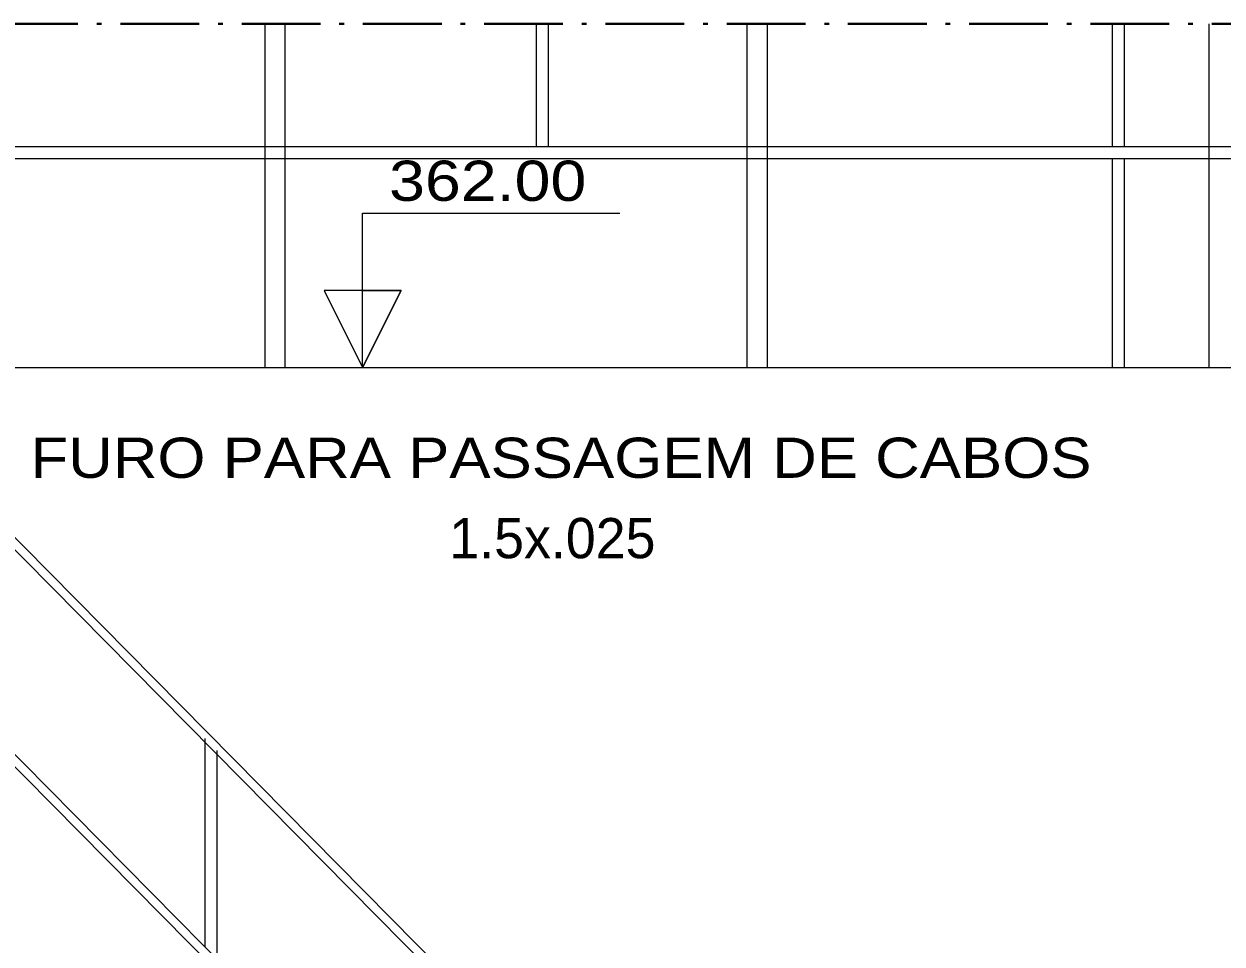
# Model space of a CAD drawing. Extents: x -4160 to -2690, y -474 to 714.
# Drawn here: x -3633.03 to -3590.42, y -282.79 to -250.08 of the extents above; entities that cross this region are included whole.
import ezdxf
from ezdxf.enums import TextEntityAlignment as Align

# ---------------------------------------------------------------- set-up
doc = ezdxf.new("R2010")
doc.units = 0
doc.header["$LTSCALE"] = 0.56
doc.linetypes.add('DOT_DASHED', pattern=[7.7, 5, -1.2, 0.3, -1.2])
for name, color, linetype, lineweight in [('10', 7, 'Continuous', 35), ('13', 7, 'Continuous', 13), ('2', 7, 'Continuous', 25), ('63', 7, 'Continuous', 13), ('9', 7, 'Continuous', 13)]:
    doc.layers.add(name, color=color, linetype=linetype, lineweight=lineweight)

msp = doc.modelspace()

# ---------------------------------------------------------------- linework, layer by layer
at = {"layer": '10', "lineweight": 13}
msp.add_line((-3651.4113, -250.077), (-3593.7271, -308.4155), dxfattribs=at)
at = {"layer": '13'}
for p, q in [((-3651.8384, -250.077), (-3594.1556, -308.4141)), ((-3614.8185, -250.077), (-3614.8185, -254.4298)), ((-3614.3899, -250.077), (-3614.3899, -254.4298)), ((-3594.3299, -250.077), (-3594.3299, -254.4298)), ((-3593.9013, -250.077), (-3593.9013, -254.4298)), ((-3654.8756, -254.287), (-3594.1556, -315.6941)), ((-3654.8756, -254.7198), (-3594.1556, -316.1283)), ((-3647.107, -254.4298), (-3573.9042, -254.4298)), ((-3646.6827, -254.8584), (-3573.9042, -254.8584)), ((-3594.3299, -254.8584), (-3594.3299, -262.287)), ((-3593.9013, -254.8584), (-3593.9013, -262.287)), ((-3655.3184, -262.287), (-3573.8899, -262.287)), ((-3626.5827, -282.9012), (-3626.5827, -275.4769)), ((-3626.1542, -283.3341), (-3626.1542, -275.9112))]:
    msp.add_line(p, q, dxfattribs=at)
at = {"layer": '2'}
msp.add_line((-3620.987, -262.2942), (-3619.6155, -259.5513), dxfattribs=at)
msp.add_lwpolyline([(-3620.987, -262.2942), (-3620.987, -259.5513), (-3619.6155, -259.5513)], close=True, dxfattribs=at)
at = {"layer": '63'}
for p, q in [((-3624.4613, -250.077), (-3624.4613, -262.287)), ((-3623.747, -250.077), (-3623.747, -262.287)), ((-3607.3185, -250.077), (-3607.3185, -262.287)), ((-3606.6042, -250.077), (-3606.6042, -262.287)), ((-3590.8899, -250.077), (-3590.8899, -262.287)), ((-3620.987, -256.8084), (-3611.8442, -256.8084)), ((-3620.987, -259.5512), (-3620.987, -256.8084)), ((-3622.3585, -259.5512), (-3620.987, -262.2941)), ((-3619.6156, -259.5512), (-3622.3585, -259.5512)), ((-3620.987, -262.2941), (-3619.6156, -259.5512))]:
    msp.add_line(p, q, dxfattribs=at)
at = {"layer": '9', "linetype": 'DOT_DASHED', "lineweight": 40}
msp.add_line((-3698.5912, -250.077), (-3552.9457, -250.077), dxfattribs=at)

# ---------------------------------------------------------------- texts
at = {"layer": '2'}
for s, width, p in [('362.00', 1.2, (-3616.5384, -256.3656)), (' FURO PARA PASSAGEM DE CABOS', 1.15, (-3614.2384, -266.2142))]:
    msp.add_text(s, height=1.429, dxfattribs=dict(at, width=width)).set_placement(p, align=Align.CENTER)
msp.add_text('1.5x.025', height=1.429, dxfattribs=at).set_placement((-3614.2377, -269.0713), align=Align.CENTER)

doc.saveas('drawing.dxf')
